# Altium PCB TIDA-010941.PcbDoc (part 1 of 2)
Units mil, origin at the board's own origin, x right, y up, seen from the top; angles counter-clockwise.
Board outline 3700 x 3700 mil, 4 copper layers (Top Layer, POWER, GROUND RETURN, Bottom Layer), stack 60.134 mil thick; 115 components, 62 nets, 289 pads, 271 vias.
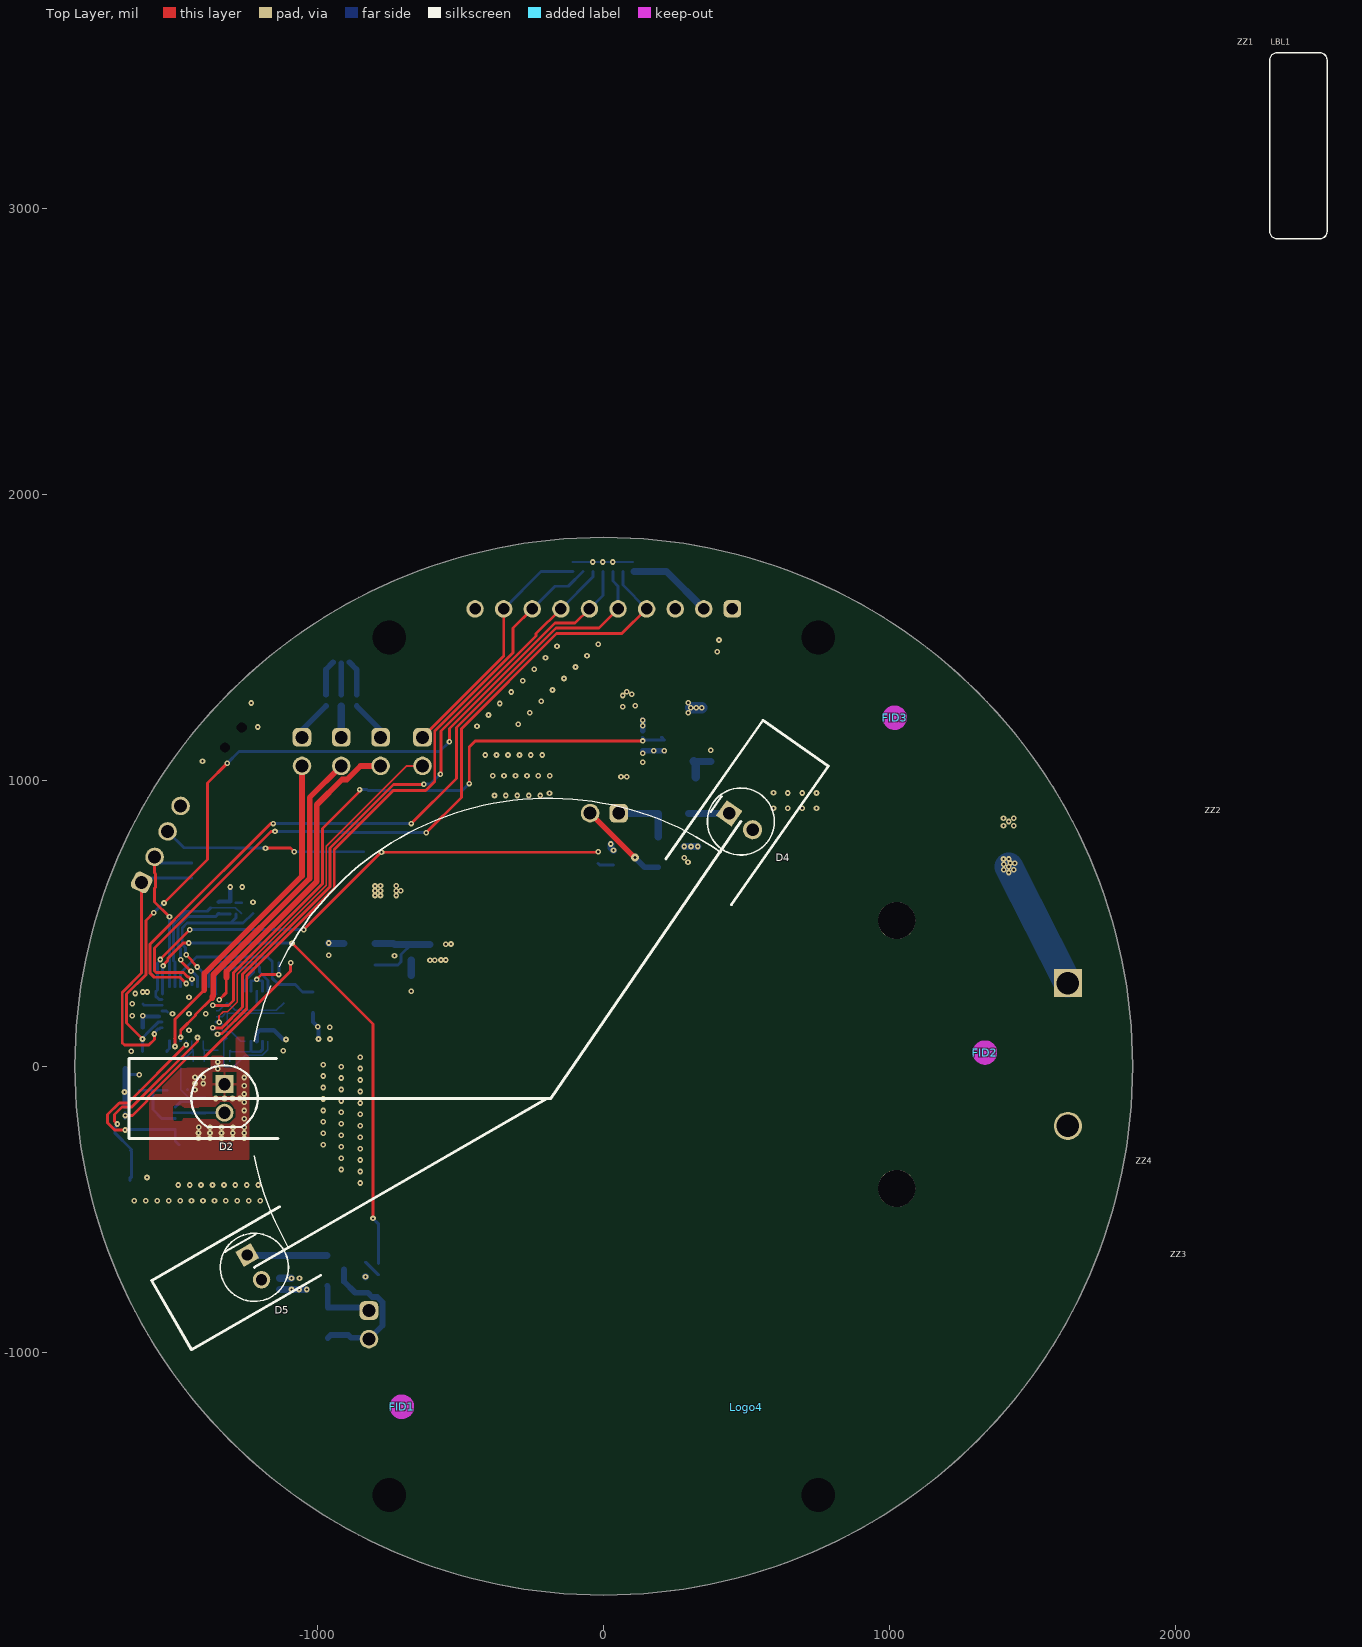
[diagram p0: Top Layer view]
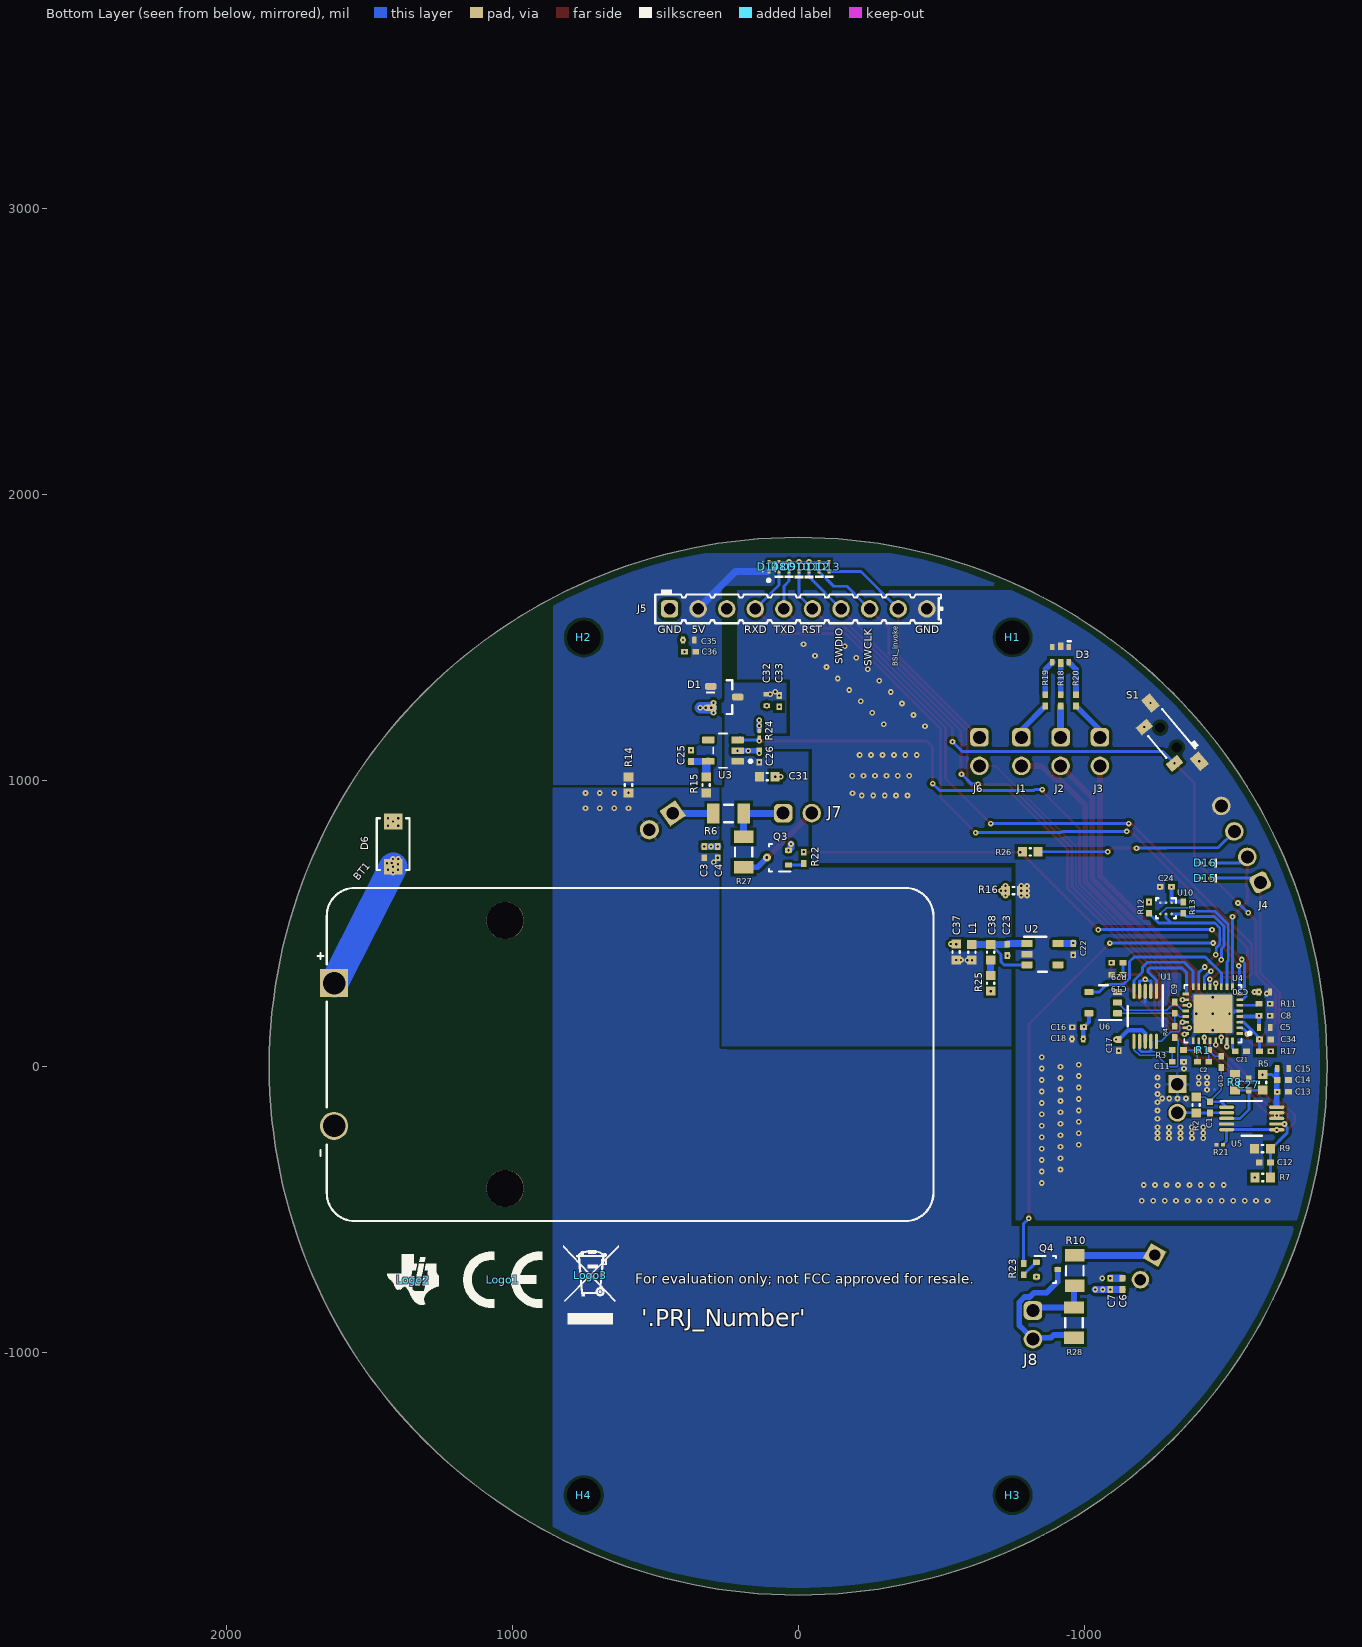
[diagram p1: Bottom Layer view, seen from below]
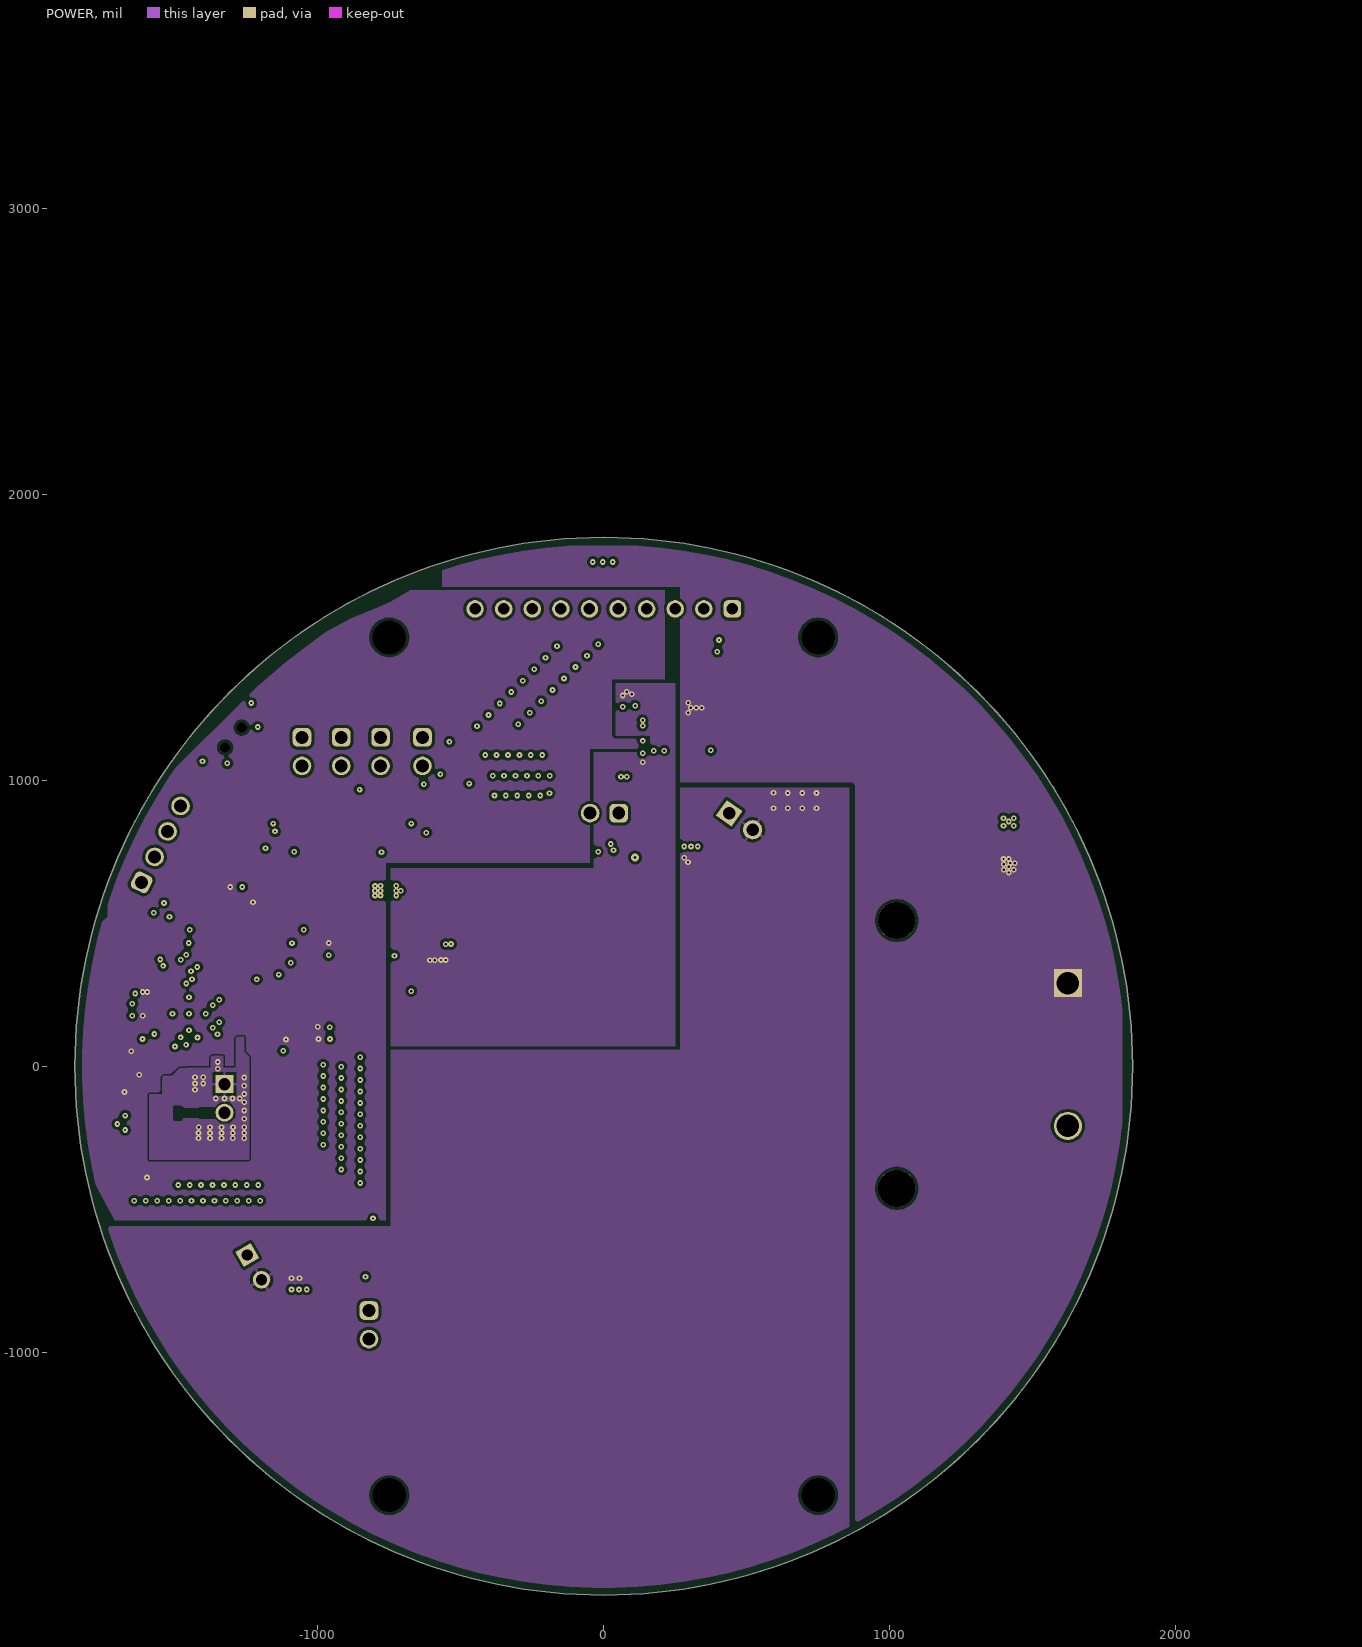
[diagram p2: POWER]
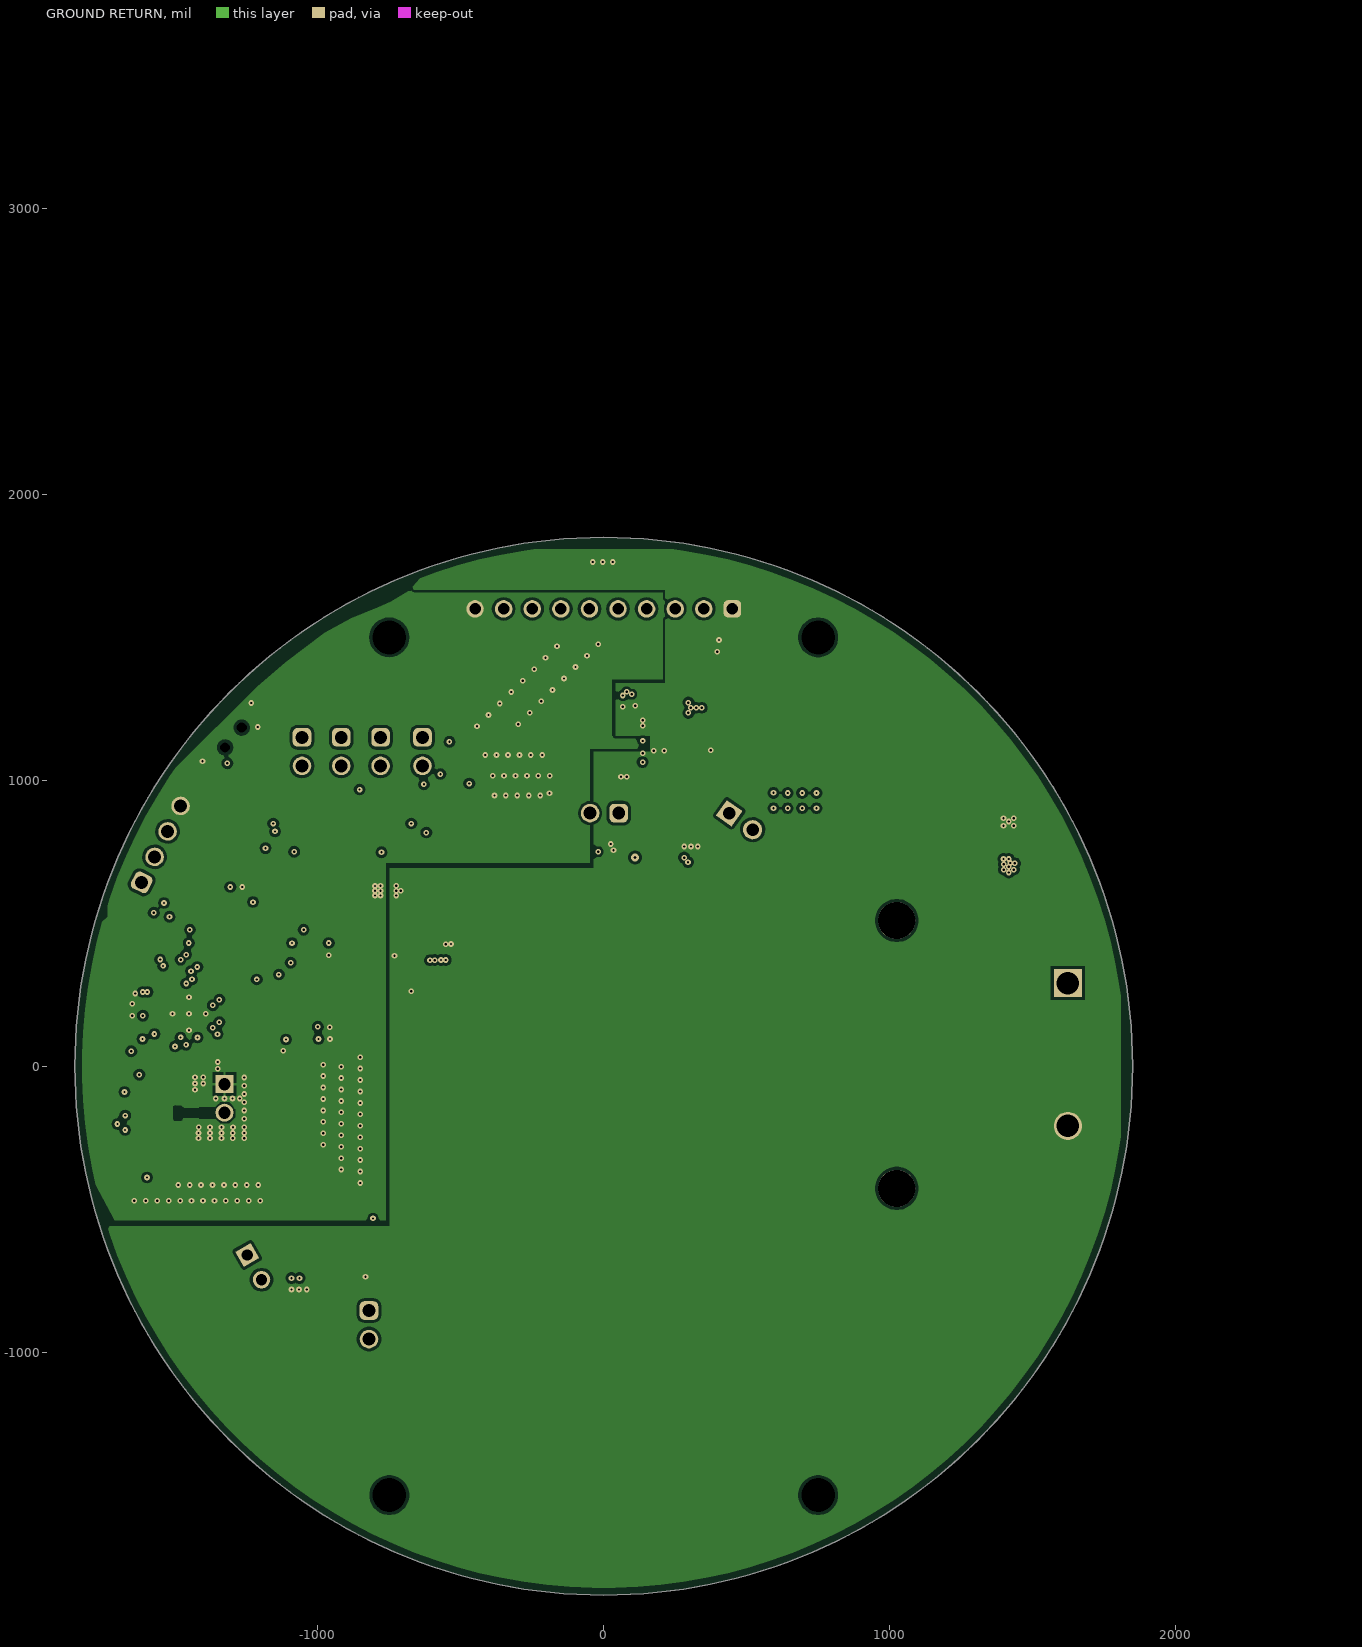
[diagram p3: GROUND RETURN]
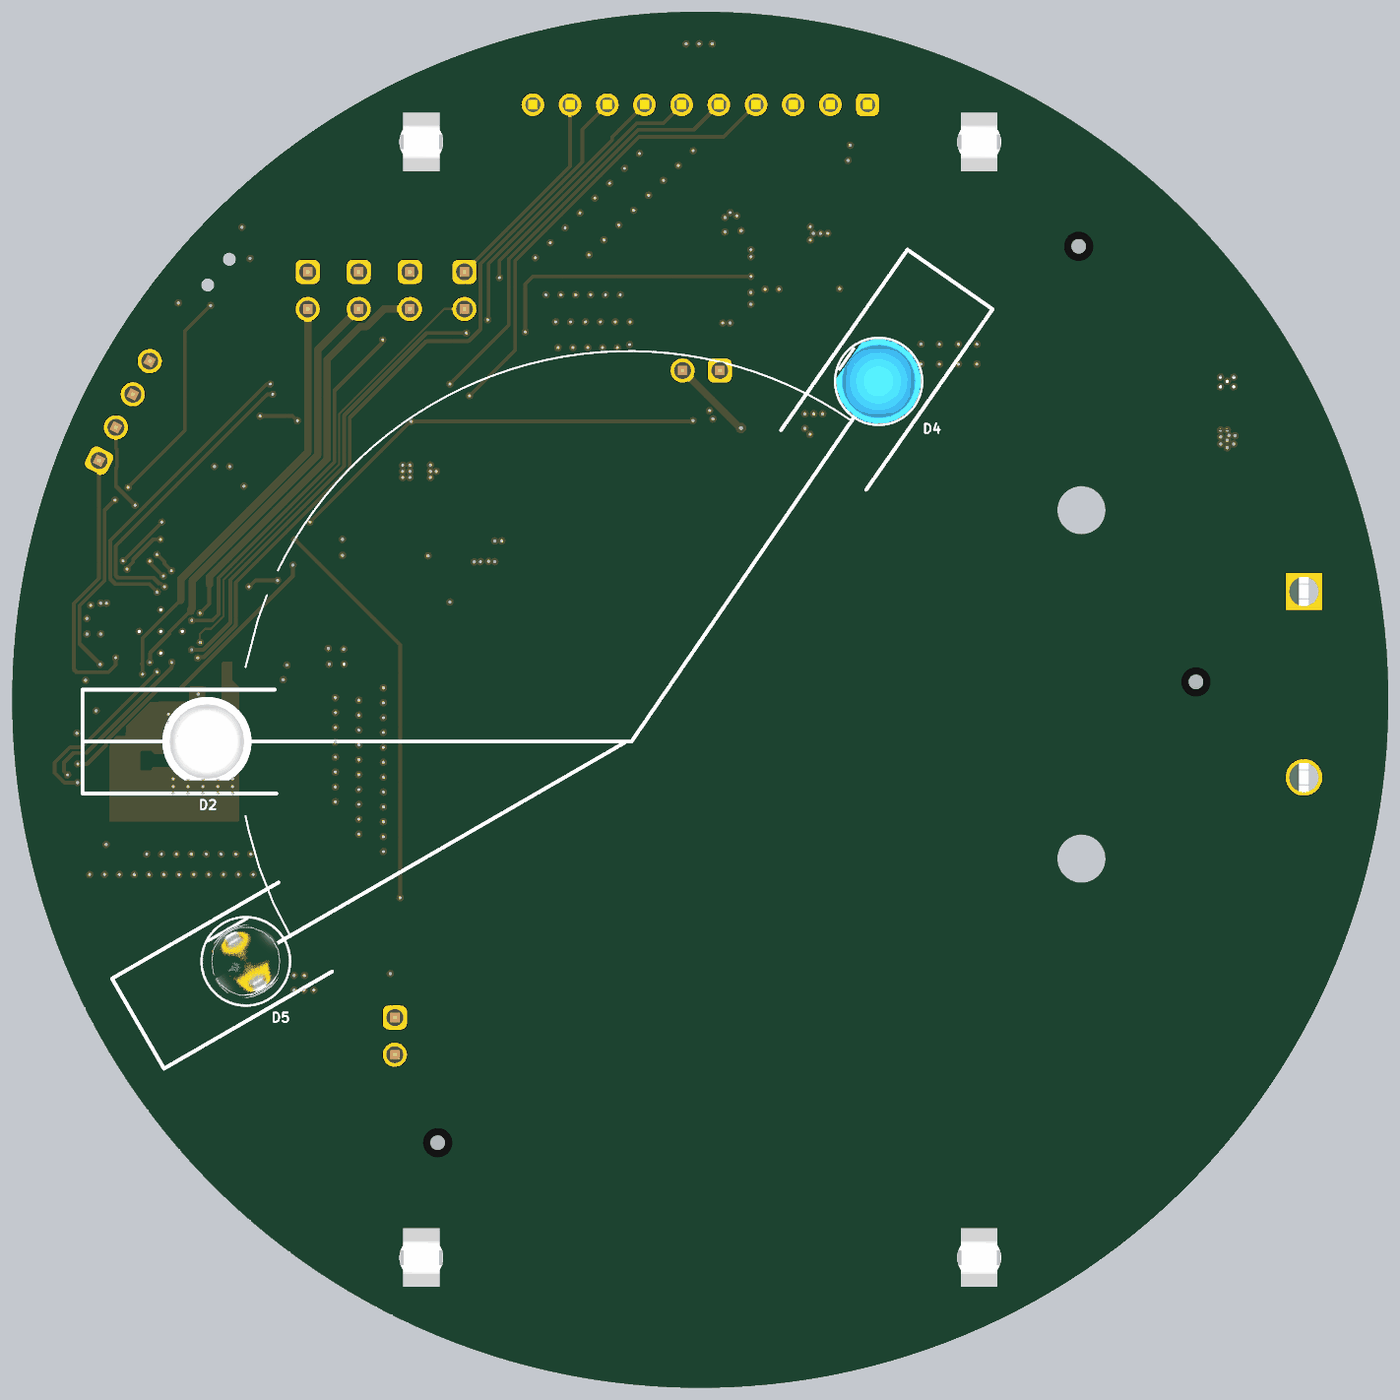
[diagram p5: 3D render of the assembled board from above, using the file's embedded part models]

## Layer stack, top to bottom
Top Solder: solder mask 0.4, Solder Resist, Dk 3.5
Top Layer: signal copper 0.689
Dielectric 1: prepreg 7, PP-006, Dk 4.2
POWER: signal copper 1.378
Dielectric2: core 42, FR-4, Dk 4.2
GROUND RETURN: signal copper 1.378
Dielectric 3: prepreg 7, PP-006, Dk 4.2
Bottom Layer: signal copper 0.689
Bottom Solder: solder mask 0.4, Solder Resist, Dk 3.5

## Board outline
0,-1850 cw(c0,0) -1850,0 cw(c0,0) 0,1850 cw(c0,0) 1850,0 cw(c0,0)

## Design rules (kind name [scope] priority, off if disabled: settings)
AcuteAngle [All] p1: minimum=4.50000000000000E+0001 checktracksonly=TRUE
AssemblyTestPointUsage [All] p1: valid=2
BoardOutlineClearance BoardOutlineClearance_S1 [InComponent('S1')] p1: gap=0 ignorepadtopadclearanceinfootprint=FALSE
BoardOutlineClearance BoardOutlineClearance_MountingHoles [OnCopper and InComponentClass('Mounting Holes')] p2: gap=39.37 ignorepadtopadclearanceinfootprint=FALSE
BoardOutlineClearance BoardOutlineClearance_Poly [OnCopper and IsPoly] p3: gap=25 ignorepadtopadclearanceinfootprint=FALSE
BoardOutlineClearance [OnCopper and Not InComponentClass('Logo') and not InComponentClass('FiducialMark') and not InRegion(1000,500,4000,800) and not InPoly] p4: gap=20 ignorepadtopadclearanceinfootprint=FALSE
Clearance Clearance_1 [InNamedPolygon('GND_GUARDRING')] p1: gap=5 ignorepadtopadclearanceinfootprint=TRUE except(0: Arc-Hole Track-Hole SMDPad-Hole THPad-Hole Via-Hole Fill-Hole Poly-Hole Region-Hole Text-Hole; 10: Arc-Text Track-Text SMDPad-Text THPad-THPad THPad-Text Via-Text Fill-Text Poly-Text Region-Text Text-Text)
Clearance Clearance_Keepouts [((IsTrack Or IsArc) And Not InPoly) And IsFree and IsKeepOut vs ((IsTrack Or IsArc) And Not InPoly) And IsFree and IsKeepOut] p2: gap=0 ignorepadtopadclearanceinfootprint=FALSE
Clearance Clearance_Poly [InPolygon] p3: gap=10 ignorepadtopadclearanceinfootprint=TRUE
Clearance Clearance_FiducialMark [IsKeepOut and InComponentClass('FiducialMark') vs IsPad and InComponentClass('FiducialMark')] p4: gap=0 ignorepadtopadclearanceinfootprint=FALSE
Clearance [All] p5: gap=5 ignorepadtopadclearanceinfootprint=TRUE except(7.87: Arc-Text Arc-Hole Track-Text Track-Hole SMDPad-Text SMDPad-Hole THPad-THPad THPad-Via THPad-Fill THPad-Poly THPad-Region THPad-Text THPad-Hole Via-Text Via-Hole Fill-Text Fill-Hole Poly-Text Poly-Hole Region-Text Region-Hole Text-Text Text-Hole)
ComponentClearance ComponentClearance_THtoSMT_D3_H1 [InComponent('D3') vs InComponent('H1')] p1: gap=10 collisioncheckmode=3 verticalgap=10 showdistances=FALSE
ComponentClearance ComponentClearance_D1 [HasFootprint('FP-TSAL6100_RADIAL-MFG')] p2: gap=0 collisioncheckmode=3 verticalgap=0 showdistances=FALSE
ComponentClearance ComponentClearance_D3 [HasFootprint('SFH_213')] p3: gap=0 collisioncheckmode=3 verticalgap=0 showdistances=FALSE
ComponentClearance componet_clearance_led_chamber_40deg_10mm_D1 [HasFootprint('FP-C503B-BAN-CY0Z0451_RADIAL-MFG') vs InComponent('D1')] p4: gap=0 collisioncheckmode=3 verticalgap=100000 showdistances=FALSE // 3d model and Diodes
ComponentClearance componet_clearance_led_chamber_40deg_10mm_D2 [HasFootprint('FP-C503B-BAN-CY0Z0451_RADIAL-MFG') vs InComponent('D2')] p5: gap=0 collisioncheckmode=3 verticalgap=100000 showdistances=FALSE // 3d model and Diodes
ComponentClearance componet_clearance_led_chamber_40deg_10mm [HasFootprint('FP-C503B-BAN-CY0Z0451_RADIAL-MFG')] p6: gap=0 collisioncheckmode=3 verticalgap=0 showdistances=FALSE // 3d model and Diodes
ComponentClearance ComponentClearance_MountingHoles_FiducialMarks [InComponentClass('Mounting Holes') vs InComponentClass('FiducialMark')] p7: gap=50 collisioncheckmode=3 verticalgap=10 showdistances=FALSE
ComponentClearance ComponentClearance_Shunt [InComponentClass('Header') vs InComponentClass('Shunt')] p8: gap=0 collisioncheckmode=3 verticalgap=0 showdistances=FALSE
ComponentClearance ComponentClearance_Logo [InComponentClass('Logo')] p9: gap=50 collisioncheckmode=3 verticalgap=10 showdistances=FALSE
ComponentClearance ComponentClearance_ScrewToNut [(HasFootprint('NY PMS 440 0025 PH')) vs (HasFootprint('Keystone_1902C'))] p10: gap=5 collisioncheckmode=3 verticalgap=10 showdistances=FALSE
ComponentClearance ComponentClearance_MountingHoles [InComponentClass('Mounting Holes')] p11: gap=250 collisioncheckmode=3 verticalgap=100000 showdistances=FALSE
ComponentClearance ComponentClearance_SmallPassives [HasFootprint('0201*') or HasFootprint('0402*') or HasFootprint('0508') or HasFootprint('0603*') or HasFootprint('0612') or HasFootprint('0805*') or HasFootprint('0815*') or HasFootprint('0830*') or HasFootprint('1206*') or HasFootprint('1210*') or HasFootprint('1808*') or HasFootprint('1812*') or HasFootprint('1825*') or HasFootprint('2010*') or HasFootprint('2220*') or HasFootprint('2225*') or HasFootprint('2512*') or HasFootprint('2728*') or HasFootprint('3518*') vs HasFootprint('0201*') or HasFootprint('0402*') or HasFootprint('0508') or HasFootprint('0603*') or HasFootprint('0612') or HasFootprint('0805*') or HasFootprint('0815*') or HasFootprint('0830*') or HasFootprint('1206*') or HasFootprint('1210*') or HasFootprint('1808*') or HasFootprint('1812*') or HasFootprint('1825*') or HasFootprint('2010*') or HasFootprint('2220*') or HasFootprint('2225*') or HasFootprint('2512*') or HasFootprint('2728*') or HasFootprint('3518*')] p12: gap=10 collisioncheckmode=3 verticalgap=10 showdistances=FALSE checkcomponentboundary=TRUE
ComponentClearance ComponentClearance_THtoSMT [IsThruComponent vs IsSMTComponent] p13: gap=40 collisioncheckmode=3 verticalgap=30 showdistances=FALSE
ComponentClearance ComponentClearance_THtoTH [IsThruComponent vs IsThruComponent] p14: gap=30 collisioncheckmode=3 verticalgap=30 showdistances=FALSE
ComponentClearance [All] p15: gap=5 collisioncheckmode=3 verticalgap=10 showdistances=FALSE
DiffPairsRouting [InDifferentialPair('LED_DEMOD_T0')] p1: maxlimit=100 minlimit=10 mostfreqgap=10 substack1={67FBA6EE-BC22-4D92-A721-B41A7FBF352C} toplayer_{67fba6ee-bc22-4d92-a721-b41a7fbf352c}_minwidth=15 toplayer_{67fba6ee-bc22-4d92-a721-b41a7fbf352c}_maxwidth=15 toplayer_{67fba6ee-bc22-4d92-a721-b41a7fbf352c}_prefwidth=15 midlayer1_{67fba6ee-bc22-4d92-a721-b41a7fbf352c}_minwidth=15 midlayer1_{67fba6ee-bc22-4d92-a721-b41a7fbf352c}_maxwidth=15 midlayer1_{67fba6ee-bc22-4d92-a721-b41a7fbf352c}_prefwidth=15 midlayer2_{67fba6ee-bc22-4d92-a721-b41a7fbf352c}_minwidth=15 midlayer2_{67fba6ee-bc22-4d92-a721-b41a7fbf352c}_maxwidth=15 midlayer2_{67fba6ee-bc22-4d92-a721-b41a7fbf352c}_prefwidth=15 bottomlayer_{67fba6ee-bc22-4d92-a721-b41a7fbf352c}_minwidth=15 bottomlayer_{67fba6ee-bc22-4d92-a721-b41a7fbf352c}_maxwidth=15 bottomlayer_{67fba6ee-bc22-4d92-a721-b41a7fbf352c}_prefwidth=15 toplayer_minwidth=15 toplayer_maxwidth=15 toplayer_prefwidth=15 midlayer1_minwidth=15 midlayer1_maxwidth=15 midlayer1_prefwidth=15 midlayer2_minwidth=15 midlayer2_maxwidth=15 midlayer2_prefwidth=15 bottomlayer_minwidth=10 bottomlayer_maxwidth=15 bottomlayer_prefwidth=15 substack2={8AD8FE77-5647-4995-9B18-3E113CC723E2} toplayer_{8ad8fe77-5647-4995-9b18-3e113cc723e2}_minwidth=15 toplayer_{8ad8fe77-5647-4995-9b18-3e113cc723e2}_maxwidth=15 toplayer_{8ad8fe77-5647-4995-9b18-3e113cc723e2}_prefwidth=15 midlayer1_{8ad8fe77-5647-4995-9b18-3e113cc723e2}_minwidth=15 midlayer1_{8ad8fe77-5647-4995-9b18-3e113cc723e2}_maxwidth=15 midlayer1_{8ad8fe77-5647-4995-9b18-3e113cc723e2}_prefwidth=15 midlayer2_{8ad8fe77-5647-4995-9b18-3e113cc723e2}_minwidth=15 midlayer2_{8ad8fe77-5647-4995-9b18-3e113cc723e2}_maxwidth=15 midlayer2_{8ad8fe77-5647-4995-9b18-3e113cc723e2}_prefwidth=15 bottomlayer_{8ad8fe77-5647-4995-9b18-3e113cc723e2}_minwidth=15 bottomlayer_{8ad8fe77-5647-4995-9b18-3e113cc723e2}_maxwidth=15 bottomlayer_{8ad8fe77-5647-4995-9b18-3e113cc723e2}_prefwidth=15 substack3={3B27082A-7492-488E-8A91-B12517C05084} toplayer_{3b27082a-7492-488e-8a91-b12517c05084}_minwidth=15 toplayer_{3b27082a-7492-488e-8a91-b12517c05084}_maxwidth=15 toplayer_{3b27082a-7492-488e-8a91-b12517c05084}_prefwidth=15 midlayer1_{3b27082a-7492-488e-8a91-b12517c05084}_minwidth=15 midlayer1_{3b27082a-7492-488e-8a91-b12517c05084}_maxwidth=15 midlayer1_{3b27082a-7492-488e-8a91-b12517c05084}_prefwidth=15 midlayer2_{3b27082a-7492-488e-8a91-b12517c05084}_minwidth=15 midlayer2_{3b27082a-7492-488e-8a91-b12517c05084}_maxwidth=15 midlayer2_{3b27082a-7492-488e-8a91-b12517c05084}_prefwidth=15 bottomlayer_{3b27082a-7492-488e-8a91-b12517c05084}_minwidth=15 bottomlayer_{3b27082a-7492-488e-8a91-b12517c05084}_maxwidth=15 bottomlayer_{3b27082a-7492-488e-8a91-b12517c05084}_prefwidth=15 substack4={4E5CCA08-6B47-41C2-A310-035C7D703A5F} toplayer_{4e5cca08-6b47-41c2-a310-035c7d703a5f}_minwidth=15 toplayer_{4e5cca08-6b47-41c2-a310-035c7d703a5f}_maxwidth=15 toplayer_{4e5cca08-6b47-41c2-a310-035c7d703a5f}_prefwidth=15 midlayer1_{4e5cca08-6b47-41c2-a310-035c7d703a5f}_minwidth=15 midlayer1_{4e5cca08-6b47-41c2-a310-035c7d703a5f}_maxwidth=15 midlayer1_{4e5cca08-6b47-41c2-a310-035c7d703a5f}_prefwidth=15 midlayer2_{4e5cca08-6b47-41c2-a310-035c7d703a5f}_minwidth=15 midlayer2_{4e5cca08-6b47-41c2-a310-035c7d703a5f}_maxwidth=15 midlayer2_{4e5cca08-6b47-41c2-a310-035c7d703a5f}_prefwidth=15 bottomlayer_{4e5cca08-6b47-41c2-a310-035c7d703a5f}_minwidth=15 bottomlayer_{4e5cca08-6b47-41c2-a310-035c7d703a5f}_maxwidth=15 bottomlayer_{4e5cca08-6b47-41c2-a310-035c7d703a5f}_prefwidth=15 filterlayerstackid={223C6A9D-A14A-4E0B-9BB0-821553589215} maxuncoupledlength=1000
FabricationTestPointUsage TestPointUsage [All] p1: valid=2 allowmultiple=FALSE
FabricationTestpoint Testpoint [All] p1: side=3 testpointundercomponent=TRUE minsize=40 maxsize=100 preferedsize=60 minholesize=0 maxholesize=40 preferedholesize=32 testpointgrid=1 allowsidetop=TRUE allowsidebottom=TRUE usegrid=TRUE gridtolerance=0.01
FanoutControl Fanout_LCC [IsLCC] p1: bgadir=Out bgaviamode=Centered fanoutstyle=Auto fanoutdirection=Alternating viagrid=1 // Fanout_LCC (Default Rule)
FanoutControl Fanout_BGA [IsBGA] p2: bgadir=Out bgaviamode=Centered fanoutstyle=Auto fanoutdirection=Alternating viagrid=1 // Fanout_BGA (Default Rule)
FanoutControl Fanout_Default [All] p4: bgadir=Out bgaviamode=Centered fanoutstyle=Auto fanoutdirection=Alternating viagrid=1 // Fanout_Default (Default Rule)
FanoutControl Fanout_Small [(CompPinCount < 5)] p5: bgadir=Out bgaviamode=Centered fanoutstyle=Auto fanoutdirection=OutThenIn viagrid=1 // Fanout_Small (Default Rule)
HoleSize [All] p1: absolutevalues=TRUE maxlimit=251 minlimit=7.87 maxpercent=80.000 minpercent=20.000
HoleToHoleClearance [All] p1: gap=5 allowstackedmicrovias=TRUE
MatchedLengths [InDifferentialPair('LED_DEMOD_T0')] p1: tolerance=1000 checknetsindiffpair=TRUE checkdiffpairvsdiffpair=FALSE checkxsignals=FALSE checkothers=FALSE usedelayunits=TRUE delaytolerance=100.000000
MinimumAnnularRing MinimumAnnularRing_ThermalPadVias [IsVia and InAnyComponent] p1: minimumring=5.91
MinimumAnnularRing [All] p2: minimumring=1.8
MinimumSolderMaskSliver MinimumSolderMaskSliver_Logo [InComponentClass('Logo') vs InComponentClass('Logo')] p1: minsoldermaskwidth=0.7
MinimumSolderMaskSliver [All] p2: minsoldermaskwidth=3
PlaneConnect [All] p1: planeconnectstyle=Relief reliefexpansion=10 reliefentries=4 reliefconductorwidth=10 reliefairgap=10
PolygonConnect [All] p1: connectstyle=Direct reliefconductorwidth=10 reliefentries=4 polygonreliefangle="90 Angle" airgapwidth=10
RoutingVias [All] p1: holewidth=8 width=26 viastyle="Through Hole" minholewidth=7.87 minwidth=16 maxholewidth=40 maxwidth=65 useviatemplates=TRUE viatemplateguid#1={75E7CF1E-CAB7-4270-AC77-309C113D3A2D} viatemplateguid#2={DC14A8CA-A990-4FAF-8852-7267901D5C4F} viatemplateguid#3={84DAFF0D-F62D-4FF4-8134-638F551A7552} viatemplateguid#4={A46787B3-2DB7-4C1C-BA2E-D92AFFC0E2DF} viatemplateguid#5={E66BFFDE-2E96-4EF7-9FE9-A94EB34D0736} viatemplatename#1=v50h20m50 viatemplatename#2=v51h20 viatemplatename#3=v51h20m56 viatemplatename#4=v71h25m0mx0 viatemplatename#5=v127h71
RoutingVias ThermalPadVias [IsVia and InAnyComponent] p2: holewidth=7.87 width=19.68 viastyle="Through Hole" minholewidth=7.87 minwidth=19.68 maxholewidth=25 maxwidth=50
SilkToBoardRegionClearance [Not ((IsComment or IsDesignator) And (Hide <> 'False')) and not InRegion(1000,500,4000,800)] p1:
SilkToSilkClearance SilkToSilkClearance_Pb-FreeLogo [(HasFootprint('Pb-Free_Overlay_Medium') OR HasFootprint('Pb-Free_Overlay_Small')) vs (HasFootprint('Pb-Free_Overlay_Medium') OR HasFootprint('Pb-Free_Overlay_Small'))] p1: silktosilkclearance=0
SilkToSilkClearance [All] p2: silktosilkclearance=3.94
SilkToSolderMaskClearance SilkToComponentPadClearance [(IsPad or IsFill or IsRegion) and InAnycomponent] p1: minsilkscreentomaskgap=2 clearancetoexposedcopper=TRUE
SilkToSolderMaskClearance "Silk to Solder Mask Opening" [All] p2: minsilkscreentomaskgap=2 clearancetoexposedcopper=FALSE
SolderMaskExpansion SolderMaskExpansion_Via [IsVia] p1: expansion=4 istentingtop=TRUE
SolderMaskExpansion [All] p2: expansion=1.97 istentingtop=FALSE
UnRoutedNet [All] p1: checkbadconnections=TRUE
Width [OnLayer('Top Layer')] p1: maxlimit=100 minlimit=6 preferedwidth=28 substack1={67FBA6EE-BC22-4D92-A721-B41A7FBF352C} toplayer_{67fba6ee-bc22-4d92-a721-b41a7fbf352c}_prefwidth=10 midlayer1_{67fba6ee-bc22-4d92-a721-b41a7fbf352c}_prefwidth=10 midlayer2_{67fba6ee-bc22-4d92-a721-b41a7fbf352c}_prefwidth=10 bottomlayer_{67fba6ee-bc22-4d92-a721-b41a7fbf352c}_prefwidth=10 toplayer_prefwidth=10 bottomlayer_prefwidth=10 substack2={8AD8FE77-5647-4995-9B18-3E113CC723E2} toplayer_{8ad8fe77-5647-4995-9b18-3e113cc723e2}_prefwidth=10 midlayer1_{8ad8fe77-5647-4995-9b18-3e113cc723e2}_prefwidth=10 midlayer2_{8ad8fe77-5647-4995-9b18-3e113cc723e2}_prefwidth=10 bottomlayer_{8ad8fe77-5647-4995-9b18-3e113cc723e2}_prefwidth=10 substack3={3B27082A-7492-488E-8A91-B12517C05084} toplayer_{3b27082a-7492-488e-8a91-b12517c05084}_prefwidth=10 midlayer1_{3b27082a-7492-488e-8a91-b12517c05084}_prefwidth=10 midlayer2_{3b27082a-7492-488e-8a91-b12517c05084}_prefwidth=10 bottomlayer_{3b27082a-7492-488e-8a91-b12517c05084}_prefwidth=10 substack4={4E5CCA08-6B47-41C2-A310-035C7D703A5F} toplayer_{4e5cca08-6b47-41c2-a310-035c7d703a5f}_prefwidth=10 midlayer1_{4e5cca08-6b47-41c2-a310-035c7d703a5f}_prefwidth=10 midlayer2_{4e5cca08-6b47-41c2-a310-035c7d703a5f}_prefwidth=10 bottomlayer_{4e5cca08-6b47-41c2-a310-035c7d703a5f}_prefwidth=10 minimp=50.000000 maximp=50.000000 favimp=50.000000 checkconnectedcopper=TRUE
13 further rules are at their usual default settings.

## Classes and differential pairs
component class Label: LBL1
component class AssemblyNote: ZZ1 ZZ2 ZZ3 ZZ4
component class M0L1306: BT1 C1 C2 C3 C4 C5 C6 C7 C8 C9 C10 C11 C12 C13 C14 C15 C16 C17 C18 C19 C21 C22 C23 C24 C25 C26 C27 C30 C31 C32 C33 C34 C35 C36 C37 C38 D1 D2 D3 D4 D5 D6 D8 D9 D10 D11 D12 D13 D14 D15 D16 J1 J2 J3 J4 J5 J6 J7 J8 L1 Q3 Q4 R1 R2 R3 R4 R5 R6 R7 R8 R9 R10 R11 R12 R13 R14 R15 R16 R17 R18 R19 R20 R21 R22 R23 R24 R25 R26 R27 R28 R29 S1 U1 U2 U3 U4 U5 U6 U10
component class Header: J1 J2 J3 J4 J5 J6 J7 J8
component class Logo: Logo2
component class Hardware: FID1 FID2 FID3 H1 H2 H3 H4 LBL1 Logo1 Logo2 Logo3 Logo4 ZZ1 ZZ2 ZZ3 ZZ4
component class FiducialMark: FID1 FID2 FID3
differential pair LED_DEMOD_T0: +LED_DEMOD_T0_P -LED_DEMOD_T0_N

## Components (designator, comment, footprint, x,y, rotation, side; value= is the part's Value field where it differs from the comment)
BT1 "1294" Keystone_1294 588,41.18 r180 bottom value="9 V"
C1 "GRM1555C1H1R9WA01D" 0402L -1440.67,-143.67 r270 bottom value=1.9pF
C2 "GRM1555C1H150JA01D" 0402L -1416.35,15.17 r180 bottom value=15pF
C3 "GRM155R61A104KA01D" 0402L 328.99,749.21 r270 bottom value=0.1uF
C4 "GRM155R61E105KA12D" 0402L 281.32,749.21 r270 bottom value=1uF
C5 "C0402C106M9PACTU" 0402_070 -1631.73,135.25 r180 bottom value=10uF
C6 "GRM155R61A104KA01D" 0402L -1134.48,-761 r90 bottom value=0.1uF
C7 "GRM155R61E105KA12D" 0402L -1092.09,-761 r90 bottom value=1uF
C8 "CMP-0006614-2" 0402L -1631.73,176.75 r180 bottom value=0.1uF
C9 "GRM1555C1E120JA01D" 0402L -1316.76,205.03 r90 bottom value=12pF
C10 "GRM1555C1H680JA01D" 0402L -1479.51,15.33 r90 bottom value=68pF
C11 "GRM1555C1H102JA01D" 0402L -1328.16,15.17 r0 bottom value=1000pF
C12 "C0402C104K8RACTU" 0402L -1632.81,-336.43 r0 bottom value=0.1uF
C13 "CMP-0006614-2" 0402L -1695.67,-89.75 r180 bottom value=0.1uF
C14 "GRM155R61E105KA12D" 0402L -1695.67,-48.16 r180 bottom value=1uF
C15 "CL05A106MP8NUB8" 0402_090S -1695.6,-7.64 r180 bottom value=10uF
C16 "CMP-0006614-2" 0402L -978.43,136.04 r0 bottom value=0.1uF
C17 "GRM155R61E105KA12D" 0402L -1121.29,73.57 r270 bottom value=1uF
C18 "CL05A106MP8NUB8" 0402_090S -977.57,95.52 r0 bottom value=10uF
C19 "GRM1555C1H102JA01D" 0402L -1116.72,320.63 r0 bottom value=1000pF
C21 "GRM155R61E474KE01D" 0402L -1548.44,52.23 r180 bottom value=0.47uF
C22 "GRM155R61E105KA12D" 0402L -962.01,409.7 r270 bottom value=1uF
C23 "GRM155R61E105KA12D" 0402L -731.95,406.7 r270 bottom value=1uF
C24 "GRM155R61A104KA01D" 0402L -1286.56,627.28 r180 bottom value=0.1uF
C25 "GRM155R61E105KA12D" 0402L 374.65,1085.49 r90 bottom value=1uF
C26 "GRM155R61E105KA12D" 0402L 136.04,1083.13 r90 bottom value=1uF
C27 "C0402C104K8RACTU" 0402L -1576.54,-64.65 r90 bottom value=0.1uF
C30 "C0402C106M9PACTU" 0402_070 -1630.74,259.76 r180 bottom value=10uF
C31 "GRM187R61A226ME15D" 0603L 107.93,1013.08 r180 bottom value=22uF
C32 "CL05A106MP8NUB8" 0402_090S 109.96,1281.26 r270 bottom value=10uF
C33 "C1005X5R1A475K050BC" 0402_065L 66.57,1277.27 r90 bottom value=4.7uF
C34 "CMP-0006673-2" 0402L -1633.25,93.74 r180 bottom value=1000pF
C35 "CL05A106MP8NUB8" 0402_090S 383.21,1491 r0 bottom value=10uF
C36 "GRM155R61A474KE15D" 0402L 377.74,1450 r180 bottom value=0.47uF
C37 "GRM187R61A226ME15D" 0603L -552.59,399.38 r90 bottom value=22uF
C38 "GRM188R61A226ME15D" 0603L -673.28,398.82 r90 bottom value=22uF
D1 "BAT54C-7-F" SOT-23 258.56,1291.32 r180 bottom value=30V
D2 "SFH 213" SFH_213 -1326.5,-112.46 r270 top
D3 "19-337/R6GHBHC-A01/2T" 19-337_RGB -918.11,1439.52 r270 bottom value=RGB
D4 "TSAL6100" FP-TSAL6100_RADIAL-MFG 479.64,856.04 r325 top locked
D5 "C503B-BAN-CZ0A0451" FP-C503B-BAN-CY0Z0451_RADIAL-MFG -1221.93,-703.41 r120 top locked
D6 "SMAJ15CA" SMA_Bi 1417,777 r270 bottom value=15V
D8 "ESD9R3.3" SOD-923 67.03,1747 r90 bottom value=3.3V
D9 "ESD9R3.3" SOD-923 32.01,1747 r90 bottom value=3.3V
D10 "ESD9R3.3" SOD-923 -3,1747 r90 bottom value=3.3V
D11 "ESD9R3.3" SOD-923 -38.01,1747 r90 bottom value=3.3V
D12 "ESD9R3.3" SOD-923 -73.03,1747 r90 bottom value=3.3V
D13 "ESD9R3.3" SOD-923 -108.03,1747 r90 bottom value=3.3V
D14 "ESD9C5.0ST5G" FP-ESD9C5.0ST5G_SOD923-MFG 102.03,1747 r90 bottom
D15 "ESD9R3.3" SOD-923 -1424.78,657.94 r0 bottom value=3.3V
D16 "ESD9R3.3" SOD-923 -1424.78,711.1 r0 bottom value=3.3V
FID1 "Fiducial" Fiducial10-20 -705.98,-1191 r0 top
FID2 "Fiducial" Fiducial10-20 1333,48 r0 top
FID3 "Fiducial" Fiducial10-20 1017.62,1219.22 r0 top
H1 "MAE-10" KY_MAE-10 -750,1500 r180 bottom locked
H2 "MAE-10" KY_MAE-10 750,1500 r180 bottom locked
H3 "MAE-10" KY_MAE-10 -750,-1500 r180 bottom locked
H4 "MAE-10" KY_MAE-10 750,-1500 r180 bottom locked
J1 "61300211121" WURTH_61300211121 -780.72,1100.65 r270 bottom
J2 "61300211121" WURTH_61300211121 -918.11,1100.65 r270 bottom
J3 "61300211121" WURTH_61300211121 -1055.5,1100.65 r270 bottom
J4 "61300411121" WURTH_61300411121 -1548.44,776.85 r63 bottom
J5 "TSW-110-08-G-S" Samtec_TSW-110-08-x-S 0,1600 r180 bottom
J6 "61300211121" WURTH_61300211121 -634,1100.65 r270 bottom
J7 "61300211121" WURTH_61300211121 2.47,885.42 r180 bottom
J8 "61300211121" WURTH_61300211121 -821.22,-904.41 r270 bottom
L1 "MPZ1608S102ATA00" 0603L -607.88,398.82 r270 bottom value="1000 ohm"
LBL1 "THT-14-423-10" Label_650x200 2430.09,3219.81 r90 top
Logo1 "CE Mark" CE_Mark_5mm 1033.84,-746.35 r180 bottom
Logo2 "Texas Instruments" TI_Symbol_Overlay_Small 1347.14,-746.35 r180 bottom
Logo3 "WEEE logo" WEEE_Minimum 726.84,-730.35 r180 bottom locked
Logo4 "FCC disclaimer" FCC_disclaimer 499,-1192 r0 top
Q3 "NX3020NAKW,115" SOT-323 71.57,729.52 r0 bottom value=30V
Q4 "NX3020NAKW,115" SOT-323 -870.89,-710.93 r180 bottom value=30V
R1 "CRCW0402150KFKED" 0402L -1416.35,56.67 r180 bottom value=150k
R2 "RG1608P-2493-B-T5" 0603L -1392.28,-135.11 r270 bottom value=249k
R3 "CRCW0402499RFKED" 0402L -1328.16,56.67 r180 bottom value=499
R4 "CRCW040228K0FKED" 0402L -1316.76,120.21 r270 bottom value=28.0k
R5 "RC0603FR-0710ML" 0603L -1624.93,-56.28 r90 bottom value=10.0Meg
R6 "ERJ-8ENF38R3V" 1206L 243.8,884.42 r180 bottom value=38.3
R7 "RC0603FR-0710ML" 0603L -1624.93,-389 r0 bottom value=10.0Meg
R8 "RC0603FR-07309KL" 0603L -1527.91,-56.28 r270 bottom value=309k
R9 "RC0603FR-0710ML" 0603L -1624.62,-288.03 r180 bottom value=10.0Meg
R10 "ERJ-8ENF1000V" 1206L -967.43,-714.85 r270 bottom value=100
R11 "RG1005P-104-B-T5" 0402L -1631.73,218.26 r180 bottom value=100k
R12 "CRCW04022K40JNED" 0402L -1227.03,554.5 r270 bottom value=2.4k
R13 "CRCW04022K40JNED" 0402L -1346.42,554.65 r270 bottom value=2.4k
R14 "RC0603JR-070RL" 0603L 593.5,984 r90 bottom value=0
R15 "RC0603JR-070RL" 0603L 321.93,984 r90 bottom value=0
R16 "RC0603JR-070RL" 0603L -753,614.26 r180 bottom value=0
R17 "CMP-0026737-1" 0402L -1633.25,52.23 r0 bottom value=47.0k
R18 "CRCW0402110RJNED" 0402L -918.11,1280.03 r90 bottom value=110
R19 "CRCW040215R0JNED" 0402L -864.37,1280.03 r90 bottom value=15
R20 "CRCW040224R0JNED" 0402L -971.85,1280.03 r270 bottom value=24
R21 "CRCW0201100KFKED" 0201L -1474.43,-274.44 r0 bottom value=100k
R22 "CRCW0402100RJNED" 0402L -19.49,728.8 r90 bottom value=100
R23 "CRCW0402100RJNED" 0402L -788.49,-709.73 r90 bottom value=100
R24 "CRCW0201100KFKED" 0201L 136.04,1161.67 r90 bottom value=100k
R25 "ERJ-3RQFR47V" 0603L -673.28,290.39 r90 bottom value=0.47
R26 "RC0603JR-070RL" 0603L -811.67,750.13 r0 bottom value=0
R27 "ERJ-8ENF38R3V" 1206L 190.85,749.18 r270 bottom value=38.3
R28 "ERJ-8ENF1000V" 1206L -965.07,-897 r270 bottom value=100
R29 "CRCW0402499RFKED" 0402L -1116.72,362.14 r0 bottom value=499
S1 "CMP-0002328-1" SW_1188E -1284.72,1140.89 r320 bottom
U1 "TS5A623157DGSR" DGS0010A_N -1213.89,174.87 r270 bottom
U2 "TPS7A2433PDBVR" DBV0005A_N -854.53,391.98 r180 bottom
U3 "TPS7A2450DBVR" DBV0005A-MFG 263.1,1103.97 r0 bottom
U4 "MSPM0L1306SRHB" RHB0032N-MFG -1450.54,183.73 r0 bottom locked
U5 "TLV9062SIDGSR" DGS0010A_N -1586.43,-182.35 r180 bottom locked
U6 "SN74LVC1G66DBVR" DBV0005A_L -1067.15,222.74 r0 bottom
U10 "HDC2010YPAR" YPA0006ABAB -1286.73,552.39 r270 bottom
ZZ1 "This Assembly Note is for PCB labels only" AssemblyNoteLabel 2237.09,-1616.19 r90 top
ZZ2 "These assemblies are ESD sensitive, ESD precautions shall be observed." AssemblyNote 2117.09,839.81 r90 top
ZZ3 "These assemblies must be clean and free from flux and all contaminants. Use of no clean flux is not acceptable." AssemblyNote 1997.09,-713.19 r90 top
ZZ4 "These assemblies must comply with workmanship standards IPC-A-610 Class 2, unless otherwise specified." AssemblyNote 1877.09,-386.19 r90 top

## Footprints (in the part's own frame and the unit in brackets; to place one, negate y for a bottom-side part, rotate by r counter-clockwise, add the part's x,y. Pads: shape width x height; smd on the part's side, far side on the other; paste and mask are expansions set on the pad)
19-337_RGB [mm] "SMD, 6-Leads, Body 1.6x1.6mm"
  rect 0.55x0.4 smd: 1(-0.675,0.725) 3(-0.675,-0.725) 4(0.675,0.725) 6(0.675,-0.725)
  rect 0.7x0.5 smd: 2(-0.75,0) 5(0.75,0)
  silkscreen extent -1.2,0.6 -1.2,0.9, body extent -0.85,-0.85 0.85,0.85, height 0.35
0201L [mm] "Data from Kemet datasheet CC101_COM dated 7/28/11"
  rect 0.36x0.32 smd mask+0.048: 1(-0.28,0) 2(0.28,0)
  body extent -0.31,-0.16 0.31,0.16, height 0.26
0402_065L [mm] "0402"
  rect 0.6x0.5 smd: 1(-0.5,0) 2(0.5,0)
  body extent -0.55,-0.3 0.55,0.3, height 0.65
0402_070 [mil] "SMD, 2-Leads, Body 1.2x0.7mm, Height 0.7mm"
  rect 15x24 smd: 1(-20,0) 2(20,0)
  body extent -24,-14 24,14, height 28
0402_090S [mil] "Based on C0402S footprint from PADS legacy"
  rrect26% 15x24 smd: 1(-20,0) 2(20,0)
  body extent -24,-14 24,14, height 35
0402L [mm] "0402 from SM-752 data"
  rect 0.6x0.5 smd: 1(-0.5,0) 2(0.5,0)
  body extent -0.55,-0.3 0.55,0.3, height 0.6
0603L [mm] "0603 from SM-752 data"
  rect 0.8x0.85 smd: 1(-0.7,0) 2(0.7,0)
  silkscreen extent -0.07,-0.33 0.07,0.33, body extent -0.87,-0.47 0.87,0.47, height 1
1206L [mm] "1206 from SM-752 data"
  rect 1.1x1.75 smd: 1(-1.35,0) 2(1.35,0)
  silkscreen extent -0.4,-0.77 0.4,0.77, body extent -1.7,-0.9 1.7,0.9, height 1.35
AssemblyNote [mil] "Assembly Note"
AssemblyNoteLabel [mil] "Assembly Note for PCB Labels"
CE_Mark_5mm [mil] "Minimum text height for CE Mark"
  silkscreen extent -138,-98 138,98
DBV0005A-MFG [mm]
  rrect17% 1.1x0.6 smd paste+0 mask+0: 1(-1.3,0.95) 2(-1.3,0) 3(-1.3,-0.95) 4(1.3,-0.95) 5(1.3,0.95)
  silkscreen extent -2.57,-1.53 0.87,1.53, body extent -1.4,-1.45 1.4,1.45, height 1.45
DBV0005A_L [mm] "SOT23, 5-Leads, Body 2.9x1.6mm, Pitch 0.95mm, Lead Span 2.8mm, IPC High Density"
  rrect18% 0.8x0.55 smd: 1(-1.275,0.95) 2(-1.275,0) 3(-1.275,-0.95) 4(1.275,-0.95) 5(1.275,0.95)
  silkscreen extent -1.63,-1.55 0.38,1.55, body extent -1.42,-1.46 1.42,1.46, height 1.09
DBV0005A_N [mm] "SOT23, 5-Leads, Body 2.9x1.6mm, Pitch 0.95mm, Lead Span 2.8mm, IPC Medium Density"
  rrect17% 1x0.6 smd: 1(-1.375,0.95) 2(-1.375,0) 3(-1.375,-0.95) 4(1.375,-0.95) 5(1.375,0.95)
  silkscreen extent -1.63,-1.55 0.38,1.55, body extent -1.42,-1.46 1.42,1.46, height 1.09
DGS0010A_N [mm] "TSSOP, 10-Leads, Body 3x3mm, Pitch 0.5mm, IPC Medium Density"
  oval 1.35x0.3 smd: 1(-2.225,1) 2(-2.225,0.5) 3(-2.225,0) 4(-2.225,-0.5) 5(-2.225,-1) 6(2.225,-1) 7(2.225,-0.5) 8(2.225,0) 9(2.225,0.5) 10(2.225,1)
  silkscreen extent -2.75,-1.55 0.9,1.55, body extent -2.45,-1.5 2.45,1.5, height 0.96
FCC_disclaimer [mil]
Fiducial10-20 [mm]
  round 1 smd mask+0.5: 1(0,0)
  Top Layer keep-out circle w1.178: c0,0 r0.5
FP-C503B-BAN-CY0Z0451_RADIAL-MFG [mm]
  rrect6% 1.55x1.55 hole 1 paste-1000 mask+0: 1(1.27,0)
  round 1.55 hole 1 paste-1000 mask+0: 2(-1.27,0)
  silkscreen extent -3.02,-3.02 3.03,3.02, body extent -3.13,-3.12 3.13,3.13, height 0.25
FP-ESD9C5.0ST5G_SOD923-MFG [mm]
  rrect40% 0.36x0.25 smd paste+0 mask+0: 1(-0.42,0) 2(0.42,0)
  silkscreen extent -1.32,-0.55 0.43,0.55, body extent -0.5,-0.3 0.5,0.3, height 0.4
FP-TSAL6100_RADIAL-MFG [mm]
  rrect6% 1.7x1.7 hole 1.1 paste-1000 mask+0: 1(-1.27,0)
  round 1.7 hole 1.1 paste-1000 mask+0: 2(1.27,0)
  silkscreen extent -2.97,-2.97 2.97,2.97, body extent -3.08,-3.08 3.08,3.07, height 0.25
Keystone_1294 [mm] "9 V Molded Battery Holder, TH"
  rect 2.5x2.5 hole 2: 1(-26.3,6.35)
  round 2.5 hole 2: 2(-26.3,-6.35)
  round 3.3 hole 3.3 unplated mask+0: MH1(-11.1,11.9) MH2(-11.1,-11.9)
  silkscreen extent -27.75,-14.8 26.95,14.8, body extent -26.95,-14.8 26.95,14.8, height 20.3
KY_MAE-10 [mm] "Spacer Nylon Support"
  round 2.8 hole 3 unplated mask+0.102: ""(0,0)
  body extent -3.19,-2.75 3.19,2.75, height 10
Label_650x200 [mil] "Thermal Transfer Label"
  round 1 on Mech13: 0(0,0)
  silkscreen extent -325,-100 325,100, body extent -325,-100 325,100, height 1
RHB0032N-MFG [mm]
  rrect40% 0.6x0.25 smd paste+0 mask+0: 1(-2.4,1.75) 2(-2.4,1.25) 3(-2.4,0.75) 4(-2.4,0.25) 5(-2.4,-0.25) 6(-2.4,-0.75) 7(-2.4,-1.25) 8(-2.4,-1.75) 17(2.4,-1.75) 18(2.4,-1.25) 19(2.4,-0.75) 20(2.4,-0.25) 21(2.4,0.25) 22(2.4,0.75) 23(2.4,1.25) 24(2.4,1.75)
  rrect40% 0.25x0.6 smd paste+0 mask+0: 9(-1.75,-2.4) 10(-1.25,-2.4) 11(-0.75,-2.4) 12(-0.25,-2.4) 13(0.25,-2.4) 14(0.75,-2.4) 15(1.25,-2.4) 16(1.75,-2.4) 25(1.75,2.4) 26(1.25,2.4) 27(0.75,2.4) 28(0.25,2.4) 29(-0.25,2.4) 30(-0.75,2.4) 31(-1.25,2.4) 32(-1.75,2.4)
  rrect3% 3.45x3.45 smd paste-1000 mask+0: 33(0,0)
  silkscreen extent -3.4,-2.55 2.55,2.55, body extent -2.5,-2.5 2.5,2.5, height 0.9
Samtec_TSW-110-08-x-S [mm] "Header, 2.54mm, 10x1, TH"
  rrect50% 1.55x1.55 hole 1.02: 1(-11.43,0)
  round 1.55 hole 1.02: 2(-8.89,0) 3(-6.35,0) 4(-3.81,0) 5(-1.27,0) 6(1.27,0) 7(3.81,0) 8(6.35,0) 9(8.89,0) 10(11.43,0)
  silkscreen extent -12.7,-1.27 12.83,1.7, body extent -12.7,-1.27 12.83,1.27, height 8.38
SFH_213 [mm] "TH, 2-Leads, Dia 5.7mm, Pin Spacing 2.54mm"
  rect 1.6x1.6 hole 1.1: 1(-1.27,0)
  round 1.6 hole 1.1: 2(1.27,0)
  silkscreen extent -2.95,-2.95 2.55,2.95, body extent -2.95,-2.95 2.55,2.95, height 11.4
SMA_Bi [mm] "SMD, 2-Leads, Body 4.275x2.575mm"
  rect 1.4x1.64 smd: 1(-2.015,0) 2(2.015,0)
  silkscreen extent -2.3,-1.45 2.3,1.45, body extent -2.52,-1.45 2.52,1.45, height 2.65
SOD-923 [mm] "ON-SEMI"
  rect 0.36x0.25 smd: 1(-0.42,0) 2(0.42,0)
  silkscreen extent -1.01,-0.38 -0.76,0.38, body extent -0.45,-0.35 0.45,0.35, height 0.44
SOT-23 [mm] "SOT23, 3-Leads, Body 2.9x1.3mm, Pitch 0.95mm, Lead Span 2.5mm, IPC Medium Density"
  rrect50% 1x0.6 smd: 1(-1.2,0.95) 2(-1.2,-0.95) 3(1.2,0)
  silkscreen extent -1.63,-1.5 0.7,1.5, body extent -1.16,-1.45 1.21,1.45, height 1
SOT-323 [mm] "Diodes Inc recommended land pattern.  2016-02-24"
  rrect21% 0.6x0.47 smd: 1(-0.95,0.65) 2(-0.95,-0.65) 3(0.95,0)
  silkscreen extent -1.14,-1.22 0.77,1.22, body extent -1.13,-1.13 1.12,1.12, height 1.13
SW_1188E [mm] "SMD, 4-Leads, Body 7.8x3.5mm"
  rrect10% 1x1.45 smd: 1(-1.1,3.375) 2(-1.1,-3.375)
  rrect11% 1.3x0.9 smd: 3(0.7,2.1) 4(0.7,-2.1)
  round 0 hole 0.9 unplated: ""(-0.35,1.15) ""(-0.35,-1.15)
  silkscreen extent -1.97,-2.28 0.95,2.28, body extent -1.65,-4.15 1.4,4.15, height 3.5
TI_Symbol_Overlay_Small [mil]
  silkscreen extent -90,-88 91,88
WEEE_Minimum [mil] "WEEElie bin"
  silkscreen extent -95,-172 99,104
WURTH_61300211121 [mm] "Header, 2.54mm, 2x1, TH"
  rrect50% 1.65x1.65 hole 1.15: 1(-1.27,0)
  round 1.65 hole 1.15: 2(1.27,0)
  body extent -2.54,-1.27 2.54,1.27, height 8.54
WURTH_61300411121 [mm] "Header, 2.54mm, 4x1, TH"
  rrect50% 1.65x1.65 hole 1.15: 1(-3.81,0)
  round 1.65 hole 1.15: 2(-1.27,0) 3(1.27,0) 4(3.81,0)
  body extent -5.08,-1.27 5.08,1.27, height 8.54
YPA0006ABAB [mm] "BGA, 6-Leads, Body1.505x1.505mm, Pitch 0.5mm"
  round 0.23 smd paste-0.13 mask+0.038: A1(-0.5,0.5) A2(0.5,0.5) B1(-0.5,0) B2(0.5,0) C1(-0.5,-0.5) C2(0.5,-0.5)
  silkscreen extent -0.89,-0.89 0.89,0.89, body extent -0.75,-0.75 0.75,0.75, height 0.68

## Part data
BT1: library part CMP-0003865-1, "9 V Molded Battery Holder, TH", Manufacturer=Keystone, Supplier Part Number 1=36-1294-ND
C1: library part CMP-0080077-1, "CAP, CERM, 1.9 pF, 50 V,+/- 3%, C0G/NP0, 0402", Cap_Case=0402, Manufacturer=MuRata, Supplier Part Number 1=490-11381-1-ND, TempCo=C0G/NP0, Tolerance_%=3%, Value2=50V, ValueDisplayed=1.9pF
C2: library part CMP-0006420-2, "CAP, CERM, 15 pF, 50 V, +/- 5%, C0G/NP0, 0402", Cap_Case=0402, Manufacturer=MuRata, Supplier Part Number 1=81-GRM1555C1H150JA1D, TempCo=C0G/NP0, Tolerance_%=5%, Value1=Unknown, Value2=50V, ValueDisplayed=15pF
C3 C6 C24: library part CMP-0006562-2, "CAP, CERM, 0.1 uF, 10 V, +/- 10%, X5R, 0402", Cap_Case=0402, Manufacturer=MuRata, Supplier Part Number 1=490-1318-1-ND, TempCo=X5R, Tolerance_%=10%, Value1=Unknown, Value2=10V, ValueDisplayed=0.1uF
C4 C7 C14 C17 C22 C23 C25 C26: library part CMP-0006608-2, "CAP, CERM, 1 uF, 25 V, +/- 10%, X5R, 0402", Cap_Case=0402, Manufacturer=MuRata, Supplier Part Number 1=490-10017-1-ND, TempCo=X5R, Tolerance_%=10%, Value1=Unknown, Value2=25V, ValueDisplayed=1uF
C5 C30: library part CMP-0081134-1, "CAP, CERM, 10 µF, 6.3 V,+/- 20%, X5R, 0402", Cap_Case=0402, Manufacturer=Kemet, Supplier Part Number 1=75Y0593, TempCo=X5R, Tolerance_%=20%, Value1="0.001 ohm", Value2=6.3V, ValueDisplayed=10µF
C8 C13 C16: "CAP, CERM, 0.1 uF, 50 V, +/- 20%, X5R, 0402", Cap_Case=0402, Manufacturer=MuRata, PartNumber=GRM155R61H104ME14D, Supplier Part Number 1=GRM155R61H104ME14D-ND, TempCo=X5R, Tolerance_%=20%, Value1=Unknown, Value2=50V, ValueDisplayed=0.1uF
C9: library part CMP-0006375-2, "CAP, CERM, 12 pF, 25 V, +/- 5%, C0G/NP0, 0402", Cap_Case=0402, Manufacturer=MuRata, Supplier Part Number 1=81-GRM1555C1E120JA1D, TempCo=C0G/NP0, Tolerance_%=5%, Value1=Unknown, Value2=25V, ValueDisplayed=12pF
C10: library part CMP-0006485-2, "CAP, CERM, 68 pF, 50 V, +/- 5%, C0G/NP0, 0402", Cap_Case=0402, Manufacturer=MuRata, Supplier Part Number 1=81-GRM1555C1H680JA1D, TempCo=C0G/NP0, Tolerance_%=5%, Value1=Unknown, Value2=50V, ValueDisplayed=68pF
C11 C19: library part CMP-0006412-2, "CAP, CERM, 1000 pF, 50 V, +/- 5%, C0G/NP0, 0402", Cap_Case=0402, Manufacturer=MuRata, Supplier Part Number 1=490-3244-1-ND, TempCo=C0G/NP0, Tolerance_%=5%, Value1=Unknown, Value2=50V, ValueDisplayed=1000pF
C12 C27: library part CMP-0078241-1, "CAP, CERM, 0.1 µF, 10 V,+/- 10%, X7R, 0402", Cap_Case=0402, Manufacturer=Kemet, Supplier Part Number 1=399-3520-1-ND, TempCo=X7R, Tolerance_%=10%, Value2=10V, ValueDisplayed=0.1µF
C15 C18 C32 C35: library part CMP-0084009-1, "CAP, CERM, 10 µF, 10 V,+/- 20%, X5R, 0402", Cap_Case=0402, Manufacturer="Samsung Electro-Mechanics", Supplier Part Number 1=1276-6830-6-ND, TempCo=X5R, Tolerance_%=20%, Value1="0.001 ohm", Value2=10V, ValueDisplayed=10µF
C21: library part CMP-0064928-2, "CAP, CERM, 0.47 uF, 25 V,+/- 10%, X5R, 0402", Cap_Case=0402, Manufacturer=MuRata, Supplier Part Number 1=490-14365-1-ND, TempCo=X5R, Tolerance_%=10%, Value1=Unknown, Value2=25V, ValueDisplayed=0.47uF
C31 C37: library part CMP-0007158-5, "CAP, CERM, 22 uF, 10 V, +/- 20%, X5R, 0603", Cap_Case=0603, Manufacturer=MuRata, Supplier Part Number 1=490-13243-1-ND, TempCo=X5R, Tolerance_%=20%, Value1=Unknown, Value2=10V, ValueDisplayed=22uF
C33: library part CMP-0006268-2, "CAP, CERM, 4.7 uF, 10 V, +/- 10%, X5R, 0402", Cap_Case=0402_065, Manufacturer=TDK, Supplier Part Number 1=445-13820-1-ND, TempCo=X5R, Tolerance_%=10%, Value1="0.003417 ohm", Value2=10V, ValueDisplayed=4.7uF
C34: "CAP, CERM, 1000 pF, 50 V, +/- 10%, X7R, 0402", Cap_Case=0402, Manufacturer=MuRata, PartNumber=GRM155R71H102KA01D, Supplier Part Number 1=490-1303-1-ND, TempCo=X7R, Tolerance_%=10%, Value1=Unknown, Value2=50V, ValueDisplayed=1000pF
C36: library part CMP-0006580-2, "CAP, CERM, 0.47 uF, 10 V, +/- 10%, X5R, 0402", Cap_Case=0402, Manufacturer=MuRata, Supplier Part Number 1=490-3264-1-ND, TempCo=X5R, Tolerance_%=10%, Value1=Unknown, Value2=10V, ValueDisplayed=0.47uF
C38: library part CMP-0007324-5, "CAP, CERM, 22 uF, 10 V, +/- 20%, X5R, 0603", Cap_Case=0603, Manufacturer=MuRata, Supplier Part Number 1=490-10476-1-ND, TempCo=X5R, Tolerance_%=20%, Value1=Unknown, Value2=10V, ValueDisplayed=22uF
D1: library part CMP-0028453-2, "Diode, Schottky, 30 V, 0.2 A, SOT-23", Manufacturer="Diodes Inc.", Value1=0.2A, Value2=0.65V
D2: library part CMP-0002012-2, "Silicon PIN Photodiode, TH", Manufacturer=OSRAM, Supplier Part Number 1=475-1077-ND
D3: library part CMP-0074720-2, "LED, RGB, TH", Color=RGB, Manufacturer=Everlight, Value2=3.8V
D4: library part CMP-0087540-1, "High Power Infrared Emitting Diode, 940 nm, GaAlAs, MQW", Color=Infrared, Manufacturer=Vishay, Power_TotalModule=160mW
D5: library part CMP-0087788-2, "Blue 470nm LED Indication - Discrete 3.2V Radial", Color=Blue, Manufacturer=Cree, Power_TotalModule=120mW
D6: library part CMP-0085006-1, "Diode, TVS, Bi, 15 V, 24.4 Vc, 400 W, 16.4 A, SMA (non-polarized)", Manufacturer=Littelfuse, Value1=24.4V
D8 D9 D10 D11 D12 D13 D15 D16: library part CMP-0005914-3, "Diode, TVS, Uni, 3.3 V, SOD-923", Manufacturer="ON Semiconductor", PartNumber=ESD9R3.3ST5G, Value1=0.15W
D14: library part CMP-0097051-1, "ESD Suppressor TVS Uni-Dir 5V 2-Pin SOD-923 T/R", Breakdown Voltage=11V, Digikey Part Number=ESD9C5.0ST5GOSCT-ND, Manufacturer=onsemi, Mouser Part Number=863-ESD9C5.0ST5G, Operating Temperature Range="-55°C to +150°C", ValueDisplayed=6pF
FID1 FID2 FID3: library part CMP-0077181-1, "Fiducial mark.  There is nothing to buy or mount.", Manufacturer=N/A
H1 H2 H3 H4: library part CMP-0077978-1, "Spacer Support, Nylon 66", Manufacturer="Kang Yang"
J1 J2 J3 J6 J7 J8: library part CMP-0054794-2, "Header, 2.54 mm, 2x1, Gold, TH", Color=Black, Manufacturer="Wurth Elektronik", Supplier Part Number 1=732-5315-ND
J4: library part CMP-0054798-2, "Header, 2.54 mm, 4x1, Gold, TH", Color=Black, Manufacturer="Wurth Elektronik", Supplier Part Number 1=732-5317-ND
J5: library part CMP-0055600-1, "Header, 2.54mm, 10x1, Gold, TH", Color=Black, Current_A=6.3A, Manufacturer=Samtec, Supplier Part Number 1=SAM1038-10-ND, Voltage_V=550V
L1: library part CMP-0003424-2, "Ferrite Bead, 1000 ohm @ 100 MHz, 0.8 A, 0603", Manufacturer=TDK, Supplier Part Number 1=445-8694-1-ND, Value1="0.3 ohm", Value2=0.8A, ValueDisplayed="1000 ohm"
LBL1: library part CMP-0003625-1, "Thermal Transfer Printable Labels, 0.650\" W x 0.200\" H - 10,000 per roll", Manufacturer=Brady, Supplier Part Number 1=97C5133
Logo1: library part CMP-0074844-1
Logo2: library part CMP-0074838-1, "Texas Instrument Corporate Signature"
Logo3: library part CMP-0074769-1
Logo4: library part CMP-0074847-1, "FCC_disclaimer"
Q3 Q4: library part CMP-0000643-2, "MOSFET, N-CH, 30 V, 0.18 A, SOT-323", Alternate Manufacturer=None, Manufacturer=Nexperia, Supplier Part Number 1=568-10508-1-ND, Value1=5, Value2="0.34 nC"
R1: library part CMP-0026021-3, "RES, 150 k, 1%, 0.063 W, AEC-Q200 Grade 0, 0402", Manufacturer=Vishay-Dale, Power_W=63mW, Supplier Part Number 1=541-150KLCT-ND, TempCo="100 ppm/C", Tolerance_%=1%, Value2=0.063W, Value_Code=150k
R2: library part CMP-0023490-3, "RES, 249 k, 0.1%, 0.1 W, 0603", Manufacturer="Susumu Co Ltd", Power_W=100mW, Supplier Part Number 1=RG16P249KBCT-ND, TempCo="25 ppm/C", Tolerance_%=0.1%, Value2=0.1W, Value_Code=249k
R3 R29: library part CMP-0026402-2, "RES, 499, 1%, 0.063 W, AEC-Q200 Grade 0, 0402", Manufacturer=Vishay-Dale, Power_W=63mW, Supplier Part Number 1=541-499LCT-ND, TempCo="100 ppm/C", Tolerance_%=1%, Value2=0.063W, Value_Code=499R, ValueDisplayed=499
R4: library part CMP-0026219-2, "RES, 28.0 k, 1%, 0.063 W, AEC-Q200 Grade 0, 0402", Manufacturer=Vishay-Dale, Power_W=63mW, Supplier Part Number 1=541-28.0KLCT-ND, TempCo="100 ppm/C", Tolerance_%=1%, Value2=0.063W, Value_Code=28k0, ValueDisplayed=28.0k
R5 R7 R9: library part CMP-0022747-4, "RES, 10.0 M, 1%, 0.1 W, 0603", Manufacturer=Yageo, Power_W=100mW, Supplier Part Number 1=311-10.0MHRCT-ND, TempCo="100 ppm/C", Tolerance_%=1%, Value2=0.1W, Value_Code=10M0, ValueDisplayed=10.0M
R6 R27: library part CMP-0017576-3, "RES, 38.3, 1%, 0.25 W, AEC-Q200 Grade 0, 1206", Manufacturer=Panasonic, Power_W=250mW, Supplier Part Number 1=P38.3FCT-ND, TempCo="100 ppm/C", Tolerance_%=1%, Value2=0.25W, Value_Code=38R3, ValueDisplayed=38.3
R8: library part CMP-0023016-4, "RES, 309 k, 1%, 0.1 W, 0603", Manufacturer=Yageo, Power_W=100mW, Supplier Part Number 1=311-309KHRCT-ND, TempCo="100 ppm/C", Tolerance_%=1%, Value2=0.1W, Value_Code=309k
R10 R28: library part CMP-0017282-3, "RES, 100, 1%, 0.25 W, AEC-Q200 Grade 0, 1206", Manufacturer=Panasonic, Power_W=250mW, Supplier Part Number 1=P100FCT-ND, TempCo="100 ppm/C", Tolerance_%=1%, Value2=0.25W, Value_Code=100R, ValueDisplayed=100
R11: library part CMP-0026815-1, "RES, 100 k, 0.1%, 0.063 W, 0402", Manufacturer="Susumu Co Ltd", Power_W=63mW, Supplier Part Number 1=RG10P100KBCT-ND, TempCo="25 ppm/C", Tolerance_%=0.1%, Value2=0.063W, Value_Code=100k
R12 R13: library part CMP-0026891-5, "RES, 2.4 k, 5%, 0.063 W, AEC-Q200 Grade 0, 0402", Manufacturer=Vishay-Dale, Power_W=63mW, Supplier Part Number 1=541-2.4KJCT-ND, TempCo="200 ppm/C", Tolerance_%=5%, Value2=0.063W, Value_Code=2k40, ValueDisplayed=2.4k
R14 R15 R16 R26: library part CMP-0025885-5, "RES, 0, 5%, 0.1 W, 0603", Manufacturer=Yageo, Power_W=100mW, Supplier Part Number 1=311-0.0GRCT-ND, TempCo="200 ppm/C", Tolerance_%=5%, Value2=0.1W, Value_Code=0000, ValueDisplayed=0
R17: "RES, 47.0 k, 1%, 0.0625 W, 0402", Manufacturer="Yageo America", PartNumber=RC0402FR-0747KL, Power_W=62.5mW, Supplier Part Number 1=311-47.0KLRCT-ND, TempCo="100 ppm/C", Tolerance_%=1%, Value2=0.0625W, Value_Code=47k0, ValueDisplayed=47.0k
R18: library part CMP-0026829-3, "RES, 110, 5%, 0.063 W, AEC-Q200 Grade 0, 0402", Manufacturer=Vishay-Dale, Power_W=63mW, Supplier Part Number 1=541-110JCT-ND, TempCo="200 ppm/C", Tolerance_%=5%, Value2=0.063W, Value_Code=110R, ValueDisplayed=110
R19: library part CMP-0026843-3, "RES, 15, 5%, 0.063 W, AEC-Q200 Grade 0, 0402", Manufacturer=Vishay-Dale, Power_W=63mW, Supplier Part Number 1=541-15JCT-ND, TempCo="200 ppm/C", Tolerance_%=5%, Value2=0.063W, Value_Code=15R0, ValueDisplayed=15
R20: library part CMP-0026884-3, "RES, 24, 5%, 0.063 W, AEC-Q200 Grade 0, 0402", Manufacturer=Vishay-Dale, Power_W=63mW, Supplier Part Number 1=541-24JCT-ND, TempCo="200 ppm/C", Tolerance_%=5%, Value2=0.063W, Value_Code=24R0, ValueDisplayed=24
R21 R24: library part CMP-0027261-3, "RES, 100 k, 1%, 0.05 W, 0201", Manufacturer=Vishay-Dale, Power_W=50mW, Supplier Part Number 1=541-100KAABCT-ND, TempCo="100 ppm/C", Tolerance_%=1%, Value2=0.05W, Value_Code=100k, ValueDisplayed=100K
R22 R23: library part CMP-0026824-3, "RES, 100, 5%, 0.063 W, AEC-Q200 Grade 0, 0402", Manufacturer=Vishay-Dale, Power_W=63mW, Supplier Part Number 1=541-100JCT-ND, TempCo="200 ppm/C", Tolerance_%=5%, Value2=0.063W, Value_Code=100R, ValueDisplayed=100
R25: library part CMP-0022716-3, "RES, 0.47, 1%, 0.1 W, AEC-Q200 Grade 0, 0603", Manufacturer=Panasonic, Power_W=100mW, Supplier Part Number 1=P.47AJCT-ND, TempCo="300 ppm/C", Tolerance_%=1%, Value2=0.1W, Value_Code=R470, ValueDisplayed=0.47
S1: "Switch, SPST, 0.05 A, 12 VDC, SMD", CurrentRating_mA=50A, Manufacturer=Diptronics, PartNumber=1188E-1K2-V-TR
U1: library part CMP-0074343-1, "DUAL 10-Ohm SPDT ANALOG SWITCH WITH UNDERSHOOT/OVERSHOOT VOLTAGE PROTECTION, DGS0010A (VSSOP-10)", Alternate Manufacturer="Texas Instruments"
U2: library part CMP-0083932-1, "1µA, Ultra-Low Iq, 200mA Low-Dropout Regulator in a Small-Size Package, DBV0005A (SOT-23-5)", Alternate Manufacturer="Texas Instruments", Alternate PartNumber=TPS7A2433PDBVT, Operating Temperature Range="-40 to 125 C", Rating=Catalog
U3: library part CMP-0096923-1, "Linear Voltage Regulator IC  1 Output  200mA SOT-23-5", Digikey Part Number=296-TPS7A2450DBVRCT-ND, Dropout Voltage=160mV, Manufacturer="Texas Instruments", Max Supply Voltage=18V, Min Supply Voltage=2.4V, Mouser Part Number=595-TPS7A2450DBVR, Nominal Supply Current=2-15uA, Operating Temperature Range="-40°C to +125°C", Output Voltage=5V
U4: library part CMP-0093968-1, "MSPM0L130x Mixed-Signal Microcontrollers", Frequency_Fixed=32MHz, Manufacturer="Texas Instruments", Max Supply Voltage=3.6V, Min Supply Voltage=1.62V, Operating Temperature Range="-40°C to +125°C"
U5: library part CMP-0861005-1, "10-MHz, low-noise, RRIO, CMOS operational amplifier for cost-sensitive systems, DGS0010A (VSSOP-10)", Alternate Manufacturer="Texas Instruments", Operating Temperature Range="-40 to 125 C", Rating=Catalog
U6: library part CMP-0051071-2, "Single Analog Switch, DBV0005A (SOT-23-5)", F @ Nom Voltage(Max)(Mhz)=150, Generic Part Number=SN74LVC1G66, ICC @ Nom Voltage(Max)(mA)=0.01, Manufacturer="Texas Instruments", Operating Temperature Range="-40 to 85 C", Rating=Catalog, tpd @ Nom Voltage(Max)(ns)=2,1.2,0.8,0.6, Voltage(Nom)(V)=1.8,2.5,3.3,5
U10: library part CMP-0014223-3, "HDC2010 Low Power Humidity and Temperature Digital Sensor, YPA0006ABAB (DSBGA-6)", Alternate Manufacturer="Texas Instruments", Alternate PartNumber=HDC2010YPAT
ZZ1: library part CMP-0003616-3
ZZ2: library part CMP-0077236-1
ZZ3: library part CMP-0077237-1
ZZ4: library part CMP-0077238-1

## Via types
v1: diameter 20, hole 8, Top Layer to Bottom Layer, tented both sides, 215 vias
v2: diameter 19.68, hole 7.87, Top Layer to Bottom Layer, 48 vias
v3: diameter 20, hole 8, Top Layer to Bottom Layer, 7 vias
v4: diameter 28, hole 10, Top Layer to Bottom Layer, tented both sides, 1 vias

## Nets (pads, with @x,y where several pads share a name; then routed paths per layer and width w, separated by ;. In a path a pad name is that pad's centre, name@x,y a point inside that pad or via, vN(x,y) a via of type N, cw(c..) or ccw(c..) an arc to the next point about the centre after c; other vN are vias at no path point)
3V3: C5.1 C8.1 C13.1 C14.1 C15.1 C16.1 C17.1 C18.1 C22.1 C24.2 C30.1 R5.2 R7.2 R12.1 R13.1 R17.1 U1.8 U2.5 U4.4 U5.10 U6.5 U10.A1 | length 671.1
  Bottom Layer w10: C14.1@-1675.98,-48.16 -1673.89,-46.06 -1656.55,-28.72 R5.2@-1624.93,-28.72 ; C15.1@-1675.6,-7.64 C15.1@-1674.03,-9.21 ; v1(-1612.05,176.75) -1610.61,175.32 C8.1@-1609.18,173.89
  Bottom Layer w15: C5.1@-1612.04,135.25 v1(-1612.05,176.75) ; C8.1@-1609.18,173.89 U4.4@-1556.84,173.89 ; R13.1@-1346.42,574.33 -1344.15,576.6 -1306.41,576.6 -1306.25,576.77 v1(-1306.25,627.28) ; U1.8@-1213.89,87.27 -1213.89,114.29 -1201.83,126.35 -1154.37,126.35 C17.1@-1121.29,93.26 ; U6.5@-1016.95,185.34 -1016.95,154.88 C16.1@-998.12,136.04 -997.57,135.49 v1(-997.57,95.52)
  Bottom Layer w20: C15.1@-1674.03,-9.21 -1673.89,-46.06 -1673.88,-48.15 -1673.72,-89.74 U5.10@-1673.54,-139.05
  Bottom Layer w25: v1(-962.01,431.35) -960.04,429.39 U2.5@-908.66,429.39
  other v1: -1597.37,-389 -1675.98,-89.75 -1624.48,-29.46 -1652.94,52.23 -1111.44,93.26 -1000.08,138.01 -1612.04,259.76 -1596.29,259.76 -1227.03,574.18
5V0: C3.2 C4.2 C6.2 C7.2 D4.2 D5.2 R14.1 R15.1 | length 42.4
  Bottom Layer w25: C6.2@-1134.48,-741.32 v1(-1092.09,-741.32)
  other v1: -1064.03,-741.32 295.1,713.77 281.32,729.52 593.5,902.47 643.3,902.47 694.19,902.47 744,902.47 643.3,955.95 694.19,955.95 744,955.95 593.5,956.44
BSL_invoke: D13.1 J5.9 J6.1 | length 863
  Top Layer w10: J6.1@-634,1150.65 -350,1434.65 J5.9@-350,1600
  Bottom Layer w10: J5.9@-350,1600 -219.54,1730.46 D13.1@-108.03,1730.46
EN_LDO50: R24.1 U3.3 U4.19 | length 2221.8
  Top Layer w10: v2(-1367.52,213.26) -1367.36,213.1 -1312.26,213.1 -1295.28,230.09 -1295.28,326.94 -983.72,638.5 -983.72,831.13 v2@-855.87,958.98 ; v2(-470.43,988.79) -470.43,1117.21 -449.59,1138.05 v2(136.04,1138.05)
  Bottom Layer w10: v2(-854.01,967.68) -827.59,967.68 -824.17,964.26 -494.96,964.26 v2(-470.43,988.79) ; R24.1@136.04,1150.65 145.31,1141.37 U3.3@211.91,1141.37 U3.3@202.64,1150.65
